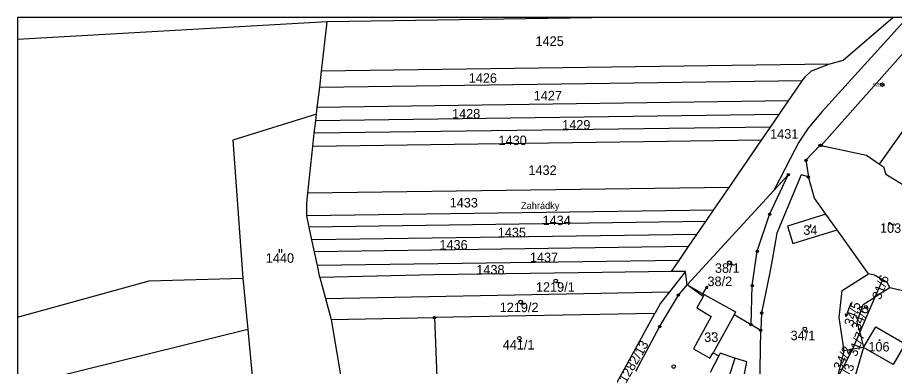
# Model space of a CAD drawing. Extents: x -564516 to -563466, y -1163913 to -1163170.
# Drawn here: x -564516.4 to -564146.8, y -1163317 to -1163170 of the extents above; entities that cross this region are included whole.
import ezdxf

# ---------------------------------------------------------------- set-up
doc = ezdxf.new("R2010")
doc.units = 0
for name, color, linetype in [('_parcely přehledka', 7, 'Continuous'), ('Hranice parcel', 7, 'Continuous'), ('Parcelní čísla', 7, 'Continuous'), ('Pop  PČ popisy', 7, 'Continuous'), ('Vnitřní kresba', 7, 'Continuous'), ('Značky bodu BP', 7, 'Continuous'), ('Značky budov', 7, 'Continuous'), ('Značky kultur', 7, 'Continuous')]:
    doc.layers.add(name, color=color, linetype=linetype)

msp = doc.modelspace()

# ---------------------------------------------------------------- linework, layer by layer
at = {"layer": '_parcely přehledka'}
msp.add_line((-563466.35, -1163170.03), (-564516.35, -1163170.03), dxfattribs=at)
msp.add_lwpolyline([(-564516.35, -1163170.03), (-564516.35, -1163912.53), (-563466.35, -1163912.53), (-563466.35, -1163170.03)], dxfattribs=at)
at = {"layer": 'Hranice parcel'}
for p, q in [((-564265, -1163170.03), (-564385.87, -1163171.82)), ((-564385.87, -1163171.82), (-564516.35, -1163179.34)), ((-564388.22, -1163192.63), (-564385.87, -1163171.82)), ((-564174.43, -1163189.7), (-564388.22, -1163192.63)), ((-564389.02, -1163199.42), (-564388.22, -1163192.63)), ((-564389.02, -1163199.42), (-564185.63, -1163196.6)), ((-564191.47, -1163205.19), (-564185.63, -1163196.6)), ((-564390.04, -1163207.94), (-564389.02, -1163199.42)), ((-564390.39, -1163210.75), (-564390.04, -1163207.94)), ((-564191.47, -1163205.19), (-564390.04, -1163207.94)), ((-564195.36, -1163210.85), (-564191.47, -1163205.19)), ((-564390.71, -1163213.52), (-564390.39, -1163210.75)), ((-564195.36, -1163210.85), (-564390.71, -1163213.52)), ((-564199.01, -1163216.17), (-564195.36, -1163210.85)), ((-564391.32, -1163218.79), (-564390.71, -1163213.52)), ((-564391.95, -1163224.33), (-564391.32, -1163218.79)), ((-564199.01, -1163216.17), (-564391.32, -1163218.79)), ((-564202.83, -1163221.74), (-564199.01, -1163216.17)), ((-564202.83, -1163221.74), (-564391.95, -1163224.33)), ((-564216.43, -1163241.57), (-564202.83, -1163221.74)), ((-564394.07, -1163244.03), (-564391.95, -1163224.33)), ((-564180.52, -1163246.18), (-564183.1, -1163237.18)), ((-564150.43, -1163236.01), (-564140.81, -1163241.88)), ((-564216.43, -1163241.57), (-564394.07, -1163244.03)), ((-564223.03, -1163251.2), (-564216.43, -1163241.57)), ((-564197.64, -1163242.84), (-564234.1, -1163282.6)), ((-564175.77, -1163252.89), (-564180.52, -1163246.18)), ((-564223.03, -1163251.2), (-564394.41, -1163253.54)), ((-564226.24, -1163255.89), (-564223.03, -1163251.2)), ((-564393.4, -1163258.3), (-564394.41, -1163253.54)), ((-564226.24, -1163255.89), (-564393.4, -1163258.3)), ((-564230.08, -1163261.47), (-564226.24, -1163255.89)), ((-564171.02, -1163259.52), (-564175.77, -1163252.89)), ((-564392.27, -1163263.69), (-564393.4, -1163258.3)), ((-564157.82, -1163277.94), (-564171.02, -1163259.52)), ((-564230.08, -1163261.47), (-564392.27, -1163263.69)), ((-564391.24, -1163268.67), (-564392.27, -1163263.69)), ((-564233.55, -1163266.53), (-564230.08, -1163261.47)), ((-564233.55, -1163266.53), (-564391.24, -1163268.67)), ((-564237.56, -1163272.38), (-564233.55, -1163266.53)), ((-564389.98, -1163274.47), (-564391.24, -1163268.67)), ((-564237.56, -1163272.38), (-564389.98, -1163274.47)), ((-564388.91, -1163279.57), (-564389.98, -1163274.47)), ((-564240.77, -1163277.05), (-564237.56, -1163272.38)), ((-564234.94, -1163276.98), (-564241.68, -1163285.61)), ((-564234.94, -1163276.98), (-564240.77, -1163277.05)), ((-564234.1, -1163282.6), (-564234.94, -1163276.98)), ((-564155.19, -1163278.6), (-564157.82, -1163277.94)), ((-564151.91, -1163280.55), (-564155.19, -1163278.6)), ((-564421.4, -1163279.88), (-564419.35, -1163301.39)), ((-564388.91, -1163279.57), (-564386.57, -1163288.41)), ((-564151.91, -1163280.55), (-564155.02, -1163287.78)), ((-564149.81, -1163281.8), (-564151.91, -1163280.55)), ((-564148.76, -1163283.85), (-564149.81, -1163281.8)), ((-564386.57, -1163288.41), (-564241.68, -1163285.61)), ((-564234.1, -1163282.6), (-564226.97, -1163286.75)), ((-564227.39, -1163287.52), (-564234.1, -1163282.6)), ((-564148.76, -1163283.85), (-564155.02, -1163287.78)), ((-564386.57, -1163288.41), (-564384.24, -1163297.26)), ((-564226.97, -1163286.75), (-564227.39, -1163287.52)), ((-564155.02, -1163287.78), (-564161.4, -1163302.6)), ((-564160.02, -1163290.92), (-564155.02, -1163287.78)), ((-564162.52, -1163298.1), (-564160.02, -1163290.92)), ((-564384.24, -1163297.26), (-564340.65, -1163296.46)), ((-564247.75, -1163294.75), (-564340.65, -1163296.46)), ((-564214.38, -1163295.21), (-564223.24, -1163311.22)), ((-564207.25, -1163299.42), (-564214.38, -1163295.21)), ((-564384.24, -1163297.26), (-564377.75, -1163335.67)), ((-564203.15, -1163301.85), (-564207.25, -1163299.42)), ((-564161.4, -1163302.6), (-564162.52, -1163298.1)), ((-564419.35, -1163301.39), (-564516.35, -1163325.53)), ((-564419.35, -1163301.39), (-564416.95, -1163326.77)), ((-564161.4, -1163302.6), (-564164.5, -1163309.79)), ((-564161.4, -1163302.6), (-564159.81, -1163309)), ((-564223.24, -1163311.22), (-564220.83, -1163312.53)), ((-564164.5, -1163309.79), (-564170.79, -1163321.81)), ((-564170.79, -1163321.81), (-564168.05, -1163310.38)), ((-564164.5, -1163309.79), (-564168.05, -1163310.38)), ((-564159.81, -1163309), (-564164.5, -1163309.79)), ((-564220.83, -1163312.53), (-564224.49, -1163319.58))]:
    msp.add_line(p, q, dxfattribs=at)
for points in [[(-564141.58, -1163170.03), (-564142.86, -1163171.64), (-564177.26, -1163209.56), (-564183.19, -1163216.68), (-564187.1, -1163222.59), (-564190.65, -1163229.22), (-564197.64, -1163242.84)], [(-564129.74, -1163170.03), (-564177.65, -1163223.93)], [(-564174.43, -1163189.7), (-564168.48, -1163187.93), (-564147.54, -1163170.03)], [(-564153.08, -1163231.82), (-564116.96, -1163180.97), (-564107.57, -1163177.86)], [(-564185.63, -1163196.6), (-564184.45, -1163194.95), (-564181.8, -1163192.51), (-564174.43, -1163189.7)], [(-564390.39, -1163210.75), (-564425.6, -1163221.69), (-564421.4, -1163279.88)], [(-564177.65, -1163223.93), (-564178.18, -1163223.81), (-564184.14, -1163230.16), (-564183.1, -1163237.18)], [(-564177.65, -1163223.93), (-564158.55, -1163228.06), (-564153.08, -1163231.82)], [(-564153.08, -1163231.82), (-564151.43, -1163232.95), (-564150.43, -1163236.01)], [(-564207.25, -1163299.42), (-564206.76, -1163282.96), (-564204.64, -1163268.51), (-564199.46, -1163252.97), (-564191.58, -1163236.23), (-564197.64, -1163242.84)], [(-564183.1, -1163237.18), (-564186.1, -1163236.26), (-564196.44, -1163260.81), (-564198.38, -1163272.04), (-564199.42, -1163278.09), (-564202.81, -1163294.5), (-564203.15, -1163301.85)], [(-564394.41, -1163253.54), (-564394.47, -1163248.16), (-564394.07, -1163244.03)], [(-564175.77, -1163252.89), (-564191.93, -1163257.87), (-564189.65, -1163265.27), (-564171.02, -1163259.52)], [(-564240.77, -1163277.05), (-564269.98, -1163277.43), (-564340.9, -1163278.42), (-564388.91, -1163279.57)], [(-564168.05, -1163310.38), (-564170.12, -1163296.33), (-564168.92, -1163285.05), (-564157.82, -1163277.94)], [(-564516.35, -1163296.3), (-564460.86, -1163280.89), (-564421.4, -1163279.88)], [(-564255.82, -1163318.97), (-564245.76, -1163300.32), (-564237.88, -1163286.97), (-564234.75, -1163283.36), (-564234.1, -1163282.6)], [(-564241.68, -1163285.61), (-564245.42, -1163290.39), (-564247.75, -1163294.75)], [(-564119.51, -1163289.97), (-564128.93, -1163288.56), (-564148.76, -1163283.85)], [(-564227.39, -1163287.52), (-564230.07, -1163292.39), (-564224.03, -1163295.93), (-564231.51, -1163309.53), (-564224.57, -1163313.53), (-564223.74, -1163312.09), (-564223.24, -1163311.22)], [(-564226.97, -1163286.75), (-564213.75, -1163294.07), (-564214.38, -1163295.21)], [(-564340.65, -1163296.46), (-564339.73, -1163321.6), (-564339.51, -1163327.45)], [(-564304.77, -1163386.26), (-564295.23, -1163376.85), (-564283.56, -1163360.04), (-564247.75, -1163294.75)], [(-564147.35, -1163316.17), (-564159.81, -1163309), (-564154.68, -1163300.34)], [(-564154.68, -1163300.34), (-564142.31, -1163307.51), (-564147.35, -1163316.17)], [(-564201.36, -1163329.93), (-564203.52, -1163326.2), (-564203.15, -1163301.85)], [(-564211.18, -1163325.92), (-564209.08, -1163315.11), (-564214.08, -1163313.46), (-564220.25, -1163311.42), (-564220.83, -1163312.53)], [(-564159.81, -1163309), (-564165.88, -1163329.53), (-564170.08, -1163335.05)]]:
    msp.add_lwpolyline(points, dxfattribs=at)
at = {"layer": 'Pop  PČ popisy'}
for p, q in [((-564227.77, -1163286.68), (-564227.2, -1163285.75)), ((-564227.2, -1163285.75), (-564225.65, -1163283.18)), ((-564225.65, -1163283.18), (-564226.6, -1163283.78)), ((-564225.65, -1163283.18), (-564225.74, -1163284.29))]:
    msp.add_line(p, q, dxfattribs=at)
at = {"layer": 'Vnitřní kresba'}
msp.add_line((-564214.08, -1163313.46), (-564217.48, -1163324.14), dxfattribs=at)
at = {"layer": 'Značky bodu BP'}
for centre, radius in [((-564151.91, -1163198.33), 0.75), ((-564151.91, -1163198.33), 0.03), ((-564178.18, -1163223.81), 0.5), ((-564178.18, -1163223.81), 0.0303), ((-564177.65, -1163223.93), 0.5), ((-564177.65, -1163223.93), 0.0303), ((-564184.14, -1163230.16), 0.5), ((-564184.14, -1163230.16), 0.0303), ((-564191.58, -1163236.23), 0.5), ((-564191.58, -1163236.23), 0.0303), ((-564183.1, -1163237.18), 0.5), ((-564183.1, -1163237.18), 0.0303), ((-564199.46, -1163252.97), 0.5), ((-564199.46, -1163252.97), 0.0303), ((-564204.64, -1163268.51), 0.5), ((-564204.64, -1163268.51), 0.0303), ((-564206.76, -1163282.96), 0.5), ((-564206.76, -1163282.96), 0.0303), ((-564237.88, -1163286.97), 0.5), ((-564237.88, -1163286.97), 0.0303), ((-564340.65, -1163296.46), 0.5), ((-564340.65, -1163296.46), 0.0303), ((-564202.81, -1163294.5), 0.5), ((-564202.81, -1163294.5), 0.0303), ((-564245.76, -1163300.32), 0.5), ((-564245.76, -1163300.32), 0.0303), ((-564207.25, -1163299.42), 0.5), ((-564207.25, -1163299.42), 0.0303), ((-564203.15, -1163301.85), 0.5), ((-564203.15, -1163301.85), 0.0303)]:
    msp.add_circle(centre, radius, dxfattribs=at)
at = {"layer": 'Značky budov'}
msp.add_line((-564148.29, -1163256.74), (-564147.99, -1163257.14), dxfattribs=at)
for centre in [(-564223.31, -1163303.03), (-564153.11, -1163305.95)]:
    msp.add_circle(centre, 0.175, dxfattribs=at)
for centre, start, end in [((-564148.8, -1163257.03), 29.2914, 181.2189), ((-564147.48, -1163256.85), 209.2914, 1.2189)]:
    msp.add_arc(centre, 0.588, start, end, dxfattribs=at)
at = {"layer": 'Značky kultur'}
for p, q in [((-564183.03, -1163258.2), (-564182.03, -1163258.2)), ((-564182.03, -1163258.2), (-564182.03, -1163257.2)), ((-564405.92, -1163269.08), (-564405.92, -1163267.58)), ((-564404.92, -1163269.08), (-564404.92, -1163267.58)), ((-564216.42, -1163274.02), (-564214.67, -1163274.02)), ((-564289.57, -1163281.72), (-564287.82, -1163281.72)), ((-564304.38, -1163290.59), (-564302.63, -1163290.59)), ((-564165.22, -1163290.3), (-564167.27, -1163295.94)), ((-564158.87, -1163292.36), (-564157.69, -1163292.36)), ((-564167.27, -1163295.94), (-564167.41, -1163294.85)), ((-564167.27, -1163295.94), (-564166.47, -1163295.2)), ((-564184.58, -1163301.92), (-564184.58, -1163302.42)), ((-564184.58, -1163302.42), (-564183.58, -1163302.42)), ((-564304.89, -1163305.84), (-564304.89, -1163306.34)), ((-564304.89, -1163306.34), (-564303.89, -1163306.34))]:
    msp.add_line(p, q, dxfattribs=at)
for centre, radius in [((-564216.42, -1163273.27), 0.75), ((-564289.57, -1163280.97), 0.75), ((-564304.38, -1163289.84), 0.75), ((-564158.87, -1163291.86), 0.502), ((-564184.58, -1163301.17), 0.75), ((-564304.89, -1163305.09), 0.75), ((-564239.83, -1163317.07), 0.75)]:
    msp.add_circle(centre, radius, dxfattribs=at)

# ---------------------------------------------------------------- texts
at = {"layer": 'Parcelní čísla'}
for s, p in [('1425', (-564298.07, -1163181.97)), ('1426', (-564326.22, -1163197.52)), ('1427', (-564298.83, -1163204.92)), ('1428', (-564333.27, -1163212.57)), ('1429', (-564286.85, -1163217.22)), ('1431', (-564199.22, -1163221.06)), ('1430', (-564313.67, -1163223.77)), ('1432', (-564301.07, -1163236.33)), ('1433', (-564334.26, -1163250.04)), ('1434', (-564295.11, -1163257.49)), ('1435', (-564314, -1163262.57)), ('34', (-564185.24, -1163261.56)), ('103', (-564152.93, -1163260.72)), ('1436', (-564338.58, -1163267.78)), ('1440', (-564411.73, -1163273.35)), ('1437', (-564300.45, -1163273.07)), ('1438', (-564323.03, -1163278.26)), ('38/1', (-564222.47, -1163277.57)), ('1219/1', (-564297.91, -1163285.57)), ('38/2', (-564225.62, -1163283.17)), ('1219/2', (-564313.17, -1163294.14)), ('33', (-564226.98, -1163306.69)), ('34/1', (-564190.59, -1163305.97)), ('441/1', (-564311.89, -1163309.89)), ('106', (-564157.81, -1163310.71))]:
    msp.add_text(s, height=4, dxfattribs=at).set_placement(p)
for s, rotation, p in [('31/6', 69, (-564152.7, -1163289.21)), ('34/5', 70, (-564164.43, -1163300.41)), ('34/6', 67, (-564161.5, -1163302.16)), ('31/7', 69, (-564162.83, -1163313.16)), ('1282/13', 60, (-564259.9, -1163324.34)), ('34/2', 64, (-564169.22, -1163319.09)), ('31/3', 73, (-564166.68, -1163326.57))]:
    msp.add_text(s, height=4, rotation=rotation, dxfattribs=at).set_placement(p)
at = {"layer": 'Pop  PČ popisy'}
msp.add_text('Zahrádky', height=2.9, dxfattribs=at).set_placement((-564304.18, -1163250.72))
at = {"layer": 'Značky bodu BP'}
msp.add_text('528', height=1.5, dxfattribs=at).set_placement((-564156.01, -1163199.08))

doc.saveas('drawing.dxf')
